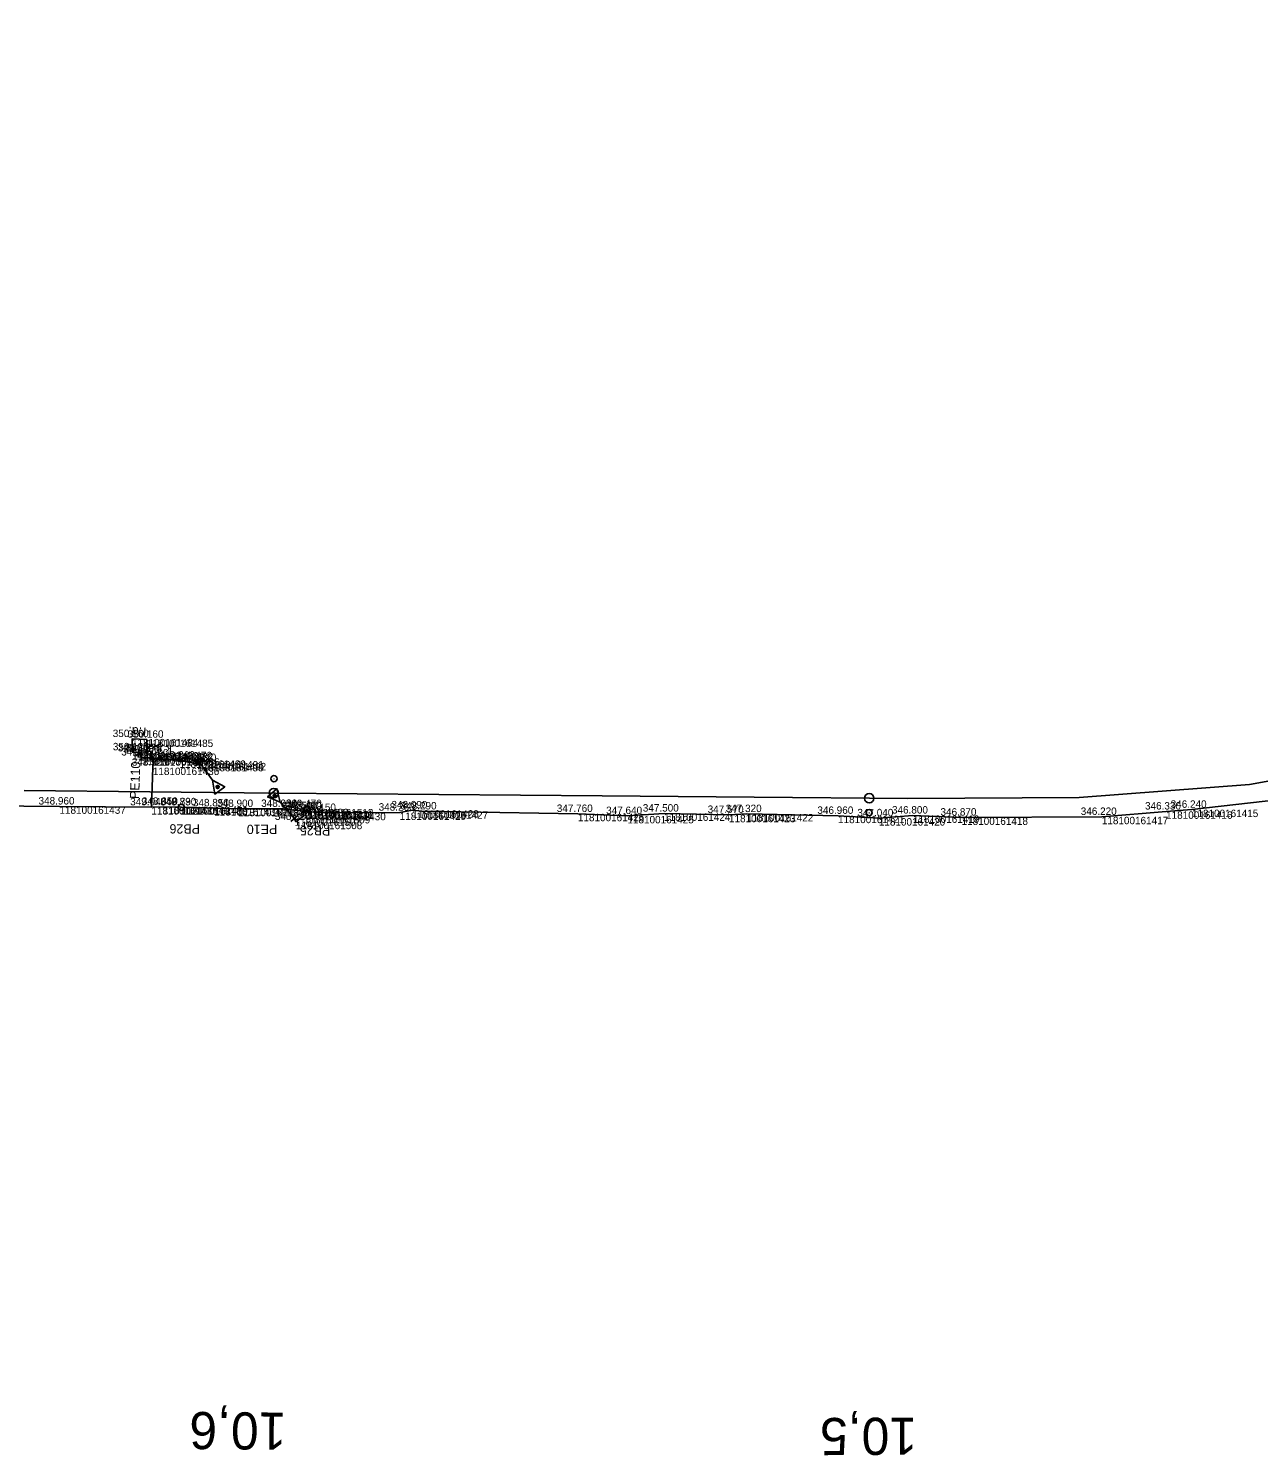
# Model space of a CAD drawing. Extents: x -732194 to -724760, y -944826 to -941477.
# Drawn here: x -727001.6 to -726803.1, y -942096.8 to -941866.5 of the extents above; entities that cross this region are included whole.
import ezdxf

# ---------------------------------------------------------------- set-up
doc = ezdxf.new("R2010")
doc.units = 0
for name, color, linetype in [('Vrstva 1', 7, 'Continuous'), ('Vrstva 25', 7, 'Continuous'), ('Vrstva 26', 7, 'Continuous'), ('Vrstva 28', 7, 'Continuous'), ('Vrstva 31', 7, 'Continuous'), ('Vrstva 35', 7, 'Continuous'), ('Vrstva 36', 7, 'Continuous'), ('Vrstva 4', 7, 'Continuous'), ('Vrstva 60', 7, 'Continuous'), ('Vrstva 61', 7, 'Continuous'), ('Vrstva 7', 7, 'Continuous')]:
    doc.layers.add(name, color=color, linetype=linetype)

msp = doc.modelspace()

# ---------------------------------------------------------------- linework, layer by layer
at = {"layer": 'Vrstva 1'}
msp.add_lwpolyline([(-726579.57, -941866.53), (-726589.02, -941872.75), (-726602.3, -941882.23), (-726613.83, -941891.22), (-726625.12, -941900.77), (-726638.15, -941911.63), (-726655.27, -941925.61), (-726667.22, -941934.63), (-726679.44, -941942.96), (-726693.78, -941951.66), (-726719.62, -941964.76), (-726748.05, -941975.61), (-726760.36, -941979.39), (-726775.65, -941983.31), (-726804.56, -941988.54), (-726832.05, -941990.67), (-726859.67, -941990.82), (-726884.47, -941990.59), (-726908.99, -941990.36), (-726961.75, -941989.93), (-727002.29, -941989.53)], dxfattribs=at)
at = {"layer": 'Vrstva 25'}
msp.add_lwpolyline([(-726981.83, -941983.22), (-726981.89, -941984.22), (-726983.89, -941984.1), (-726983.83, -941983.1), (-726981.83, -941983.22)], dxfattribs=at)
at = {"layer": 'Vrstva 26'}
for points in [[(-726983.77, -941983.51), (-726983.24, -941984.17), (-726981.43, -941984.32)], [(-726981.75, -941992.21), (-726981.52, -941985.82)], [(-726799.69, -941990.95), (-726813.85, -941992.61), (-726818.02, -941992.89), (-726828.39, -941993.76), (-726851.02, -941993.87), (-726858.86, -941993.54), (-726864.37, -941993.98), (-726870.95, -941993.59), (-726885.65, -941993.3), (-726888.55, -941993.44), (-726899.03, -941993.22), (-726904.94, -941993.62), (-726912.93, -941993.28), (-726938.13, -941992.88), (-726939.63, -941992.7), (-726941.68, -941993.07), (-726954.64, -941993.12), (-726956.62, -941992.91), (-726960.64, -941992.47), (-726967.75, -941992.48), (-726971.62, -941992.37), (-726976.88, -941992.2), (-726979.86, -941992.13), (-726981.75, -941992.21)]]:
    msp.add_lwpolyline(points, dxfattribs=at)
at = {"layer": 'Vrstva 28'}
for p, q in [((-726981.52, -941985.82), (-726981.43, -941984.32)), ((-726976.97, -941992.23), (-726976.87, -941992.23)), ((-726956.69, -941992.5), (-726956.59, -941992.5))]:
    msp.add_line(p, q, dxfattribs=at)
for points in [[(-726983.77, -941983.51), (-726983.24, -941984.17), (-726981.43, -941984.32)], [(-726981.43, -941984.32), (-726977.21, -941984.66), (-726974.34, -941985.23), (-726974.34, -941984.77), (-726973.95, -941985.06)], [(-726981.75, -941992.21), (-726981.52, -941985.82)], [(-726799.69, -941990.95), (-726813.85, -941992.61), (-726818.02, -941992.89), (-726828.39, -941993.76), (-726851.02, -941993.87), (-726858.86, -941993.54), (-726864.37, -941993.98), (-726870.95, -941993.59), (-726885.65, -941993.3), (-726888.55, -941993.44), (-726899.03, -941993.22), (-726904.94, -941993.62), (-726912.93, -941993.28), (-726938.13, -941992.88), (-726939.63, -941992.7), (-726941.68, -941993.07), (-726954.64, -941993.12), (-726956.62, -941992.91), (-726960.64, -941992.47), (-726967.75, -941992.48), (-726971.62, -941992.37), (-726976.88, -941992.2), (-726979.86, -941992.13), (-726981.75, -941992.21)], [(-726981.75, -941992.21), (-726996.59, -941992.08), (-727013.89, -941991.92), (-727018.46, -941992.07), (-727034.38, -941993.25), (-727040.22, -941993.1), (-727050.06, -941994.56), (-727054.5, -941995.33), (-727056.89, -941997.46), (-727059.11, -941996.17), (-727088.99, -942000.66), (-727092.7, -942002.01), (-727094.56, -942002.3)], [(-726976.88, -941992.2), (-726976.92, -941992.23)], [(-726958.65, -941994.02), (-726958.43, -941994.56), (-726957.15, -941993.63), (-726957.29, -941992.84)], [(-726956.67, -941992.79), (-726956.64, -941992.5)]]:
    msp.add_lwpolyline(points, dxfattribs=at)
for centre in [(-726976.92, -941992.23), (-726956.64, -941992.5)]:
    msp.add_circle(centre, 0.5, dxfattribs=at)
at = {"layer": 'Vrstva 31'}
for points in [[(-726799.69, -941990.95), (-726813.85, -941992.61), (-726818.02, -941992.89), (-726828.39, -941993.76), (-726851.02, -941993.87), (-726858.86, -941993.54), (-726864.37, -941993.98), (-726870.95, -941993.59), (-726885.65, -941993.3), (-726888.55, -941993.44), (-726899.03, -941993.22), (-726904.94, -941993.62), (-726912.93, -941993.28), (-726938.13, -941992.88), (-726939.63, -941992.7), (-726941.68, -941993.07), (-726954.64, -941993.12), (-726956.62, -941992.91), (-726960.64, -941992.47), (-726967.75, -941992.48), (-726971.62, -941992.37), (-726976.88, -941992.2), (-726979.86, -941992.13), (-726981.75, -941992.21)], [(-726981.75, -941992.21), (-726996.59, -941992.08), (-727013.89, -941991.92), (-727018.46, -941992.07), (-727034.38, -941993.25), (-727040.22, -941993.1), (-727050.06, -941994.56), (-727054.5, -941995.33), (-727056.89, -941997.46), (-727059.11, -941996.17), (-727088.99, -942000.66), (-727092.7, -942002.01), (-727094.56, -942002.3)]]:
    msp.add_lwpolyline(points, dxfattribs=at)
at = {"layer": 'Vrstva 35'}
for points in [[(-726981.75, -941992.21), (-726981.52, -941985.82)], [(-726956.62, -941992.91), (-726960.64, -941992.47), (-726967.75, -941992.48)]]:
    msp.add_lwpolyline(points, dxfattribs=at)
at = {"layer": 'Vrstva 36'}
msp.add_lwpolyline([(-726982.48, -941983.48), (-726984.84, -941983.33), (-726984.88, -941981.19), (-726982.49, -941981.3), (-726982.48, -941983.48)], dxfattribs=at)
at = {"layer": 'Vrstva 4'}
for p, q in [((-726973.32, -941984.6), (-726974.58, -941985.52)), ((-726971.03, -941988.71), (-726971.11, -941989.19)), ((-726961.89, -941990.65), (-726961.85, -941990.16)), ((-726959.24, -941994.53), (-726958.06, -941993.51))]:
    msp.add_line(p, q, dxfattribs=at)
for points in [[(-726973.95, -941985.06), (-726971.9, -941987.87), (-726969.92, -941988.9), (-726971.53, -941990.09), (-726971.9, -941987.87)], [(-726958.65, -941994.02), (-726960.95, -941991.41), (-726963.01, -941990.55), (-726961.51, -941989.23), (-726960.95, -941991.41)]]:
    msp.add_lwpolyline(points, dxfattribs=at)
for centre in [(-726971.07, -941988.95), (-726961.87, -941990.4)]:
    msp.add_circle(centre, 0.248, dxfattribs=at)
at = {"layer": 'Vrstva 60'}
for p, q in [((-726984.88, -941981.19), (-726984.88, -941981.19)), ((-726982.49, -941981.3), (-726982.49, -941981.3)), ((-726984.84, -941983.33), (-726984.84, -941983.33)), ((-726983.77, -941983.51), (-726983.77, -941983.51)), ((-726983.24, -941984.17), (-726983.24, -941984.17)), ((-726982.86, -941983.66), (-726982.86, -941983.66)), ((-726982.48, -941983.48), (-726982.48, -941983.48)), ((-726981.43, -941984.32), (-726981.43, -941984.32)), ((-726981.52, -941985.82), (-726981.52, -941985.82)), ((-726977.21, -941984.66), (-726977.21, -941984.66)), ((-726974.34, -941984.77), (-726974.34, -941984.77)), ((-726974.34, -941985.23), (-726974.34, -941985.23)), ((-726973.95, -941985.06), (-726973.95, -941985.06)), ((-726996.59, -941992.08), (-726996.59, -941992.08)), ((-726981.75, -941992.21), (-726981.75, -941992.21)), ((-726979.86, -941992.13), (-726979.86, -941992.13)), ((-726976.92, -941992.23), (-726976.92, -941992.23)), ((-726976.88, -941992.2), (-726976.88, -941992.2)), ((-726971.62, -941992.37), (-726971.62, -941992.37)), ((-726967.75, -941992.48), (-726967.75, -941992.48)), ((-726960.64, -941992.47), (-726960.64, -941992.47)), ((-726957.29, -941992.84), (-726957.29, -941992.84)), ((-726957.15, -941993.63), (-726957.15, -941993.63)), ((-726956.67, -941992.79), (-726956.67, -941992.79)), ((-726956.64, -941992.5), (-726956.64, -941992.5)), ((-726956.62, -941992.91), (-726956.62, -941992.91)), ((-726954.64, -941993.12), (-726954.64, -941993.12)), ((-726941.68, -941993.07), (-726941.68, -941993.07)), ((-726939.63, -941992.7), (-726939.63, -941992.7)), ((-726938.13, -941992.88), (-726938.13, -941992.88)), ((-726912.93, -941993.28), (-726912.93, -941993.28)), ((-726904.94, -941993.62), (-726904.94, -941993.62)), ((-726899.03, -941993.22), (-726899.03, -941993.22)), ((-726888.55, -941993.44), (-726888.55, -941993.44)), ((-726885.65, -941993.3), (-726885.65, -941993.3)), ((-726870.95, -941993.59), (-726870.95, -941993.59)), ((-726858.86, -941993.54), (-726858.86, -941993.54)), ((-726818.02, -941992.89), (-726818.02, -941992.89)), ((-726813.85, -941992.61), (-726813.85, -941992.61)), ((-726958.65, -941994.02), (-726958.65, -941994.02)), ((-726958.43, -941994.56), (-726958.43, -941994.56)), ((-726864.37, -941993.98), (-726864.37, -941993.98)), ((-726851.02, -941993.87), (-726851.02, -941993.87)), ((-726828.39, -941993.76), (-726828.39, -941993.76))]:
    msp.add_line(p, q, dxfattribs=at)
at = {"layer": 'Vrstva 7'}
for p, q in [((-726962.02, -941987.61), (-726961.92, -941987.61)), ((-726865.99, -941993.1), (-726865.89, -941993.11))]:
    msp.add_line(p, q, dxfattribs=at)
for centre, radius in [((-726961.97, -941987.61), 0.5), ((-726962, -941989.93), 0.75), ((-726865.92, -941990.76), 0.75), ((-726865.94, -941993.1), 0.5)]:
    msp.add_circle(centre, radius, dxfattribs=at)

# ---------------------------------------------------------------- texts
at = {"layer": 'Vrstva 25'}
msp.add_text('k.s.', height=1.5, rotation=176.3632, dxfattribs=at).set_placement((-726978.41, -941982.19))
at = {"layer": 'Vrstva 28'}
for s, rotation, p in [('PB26', 179.4375, (-726973.91, -941995)), ('PB25', 179.5341, (-726952.88, -941995.29))]:
    msp.add_text(s, height=1.5, rotation=rotation, dxfattribs=at).set_placement(p)
at = {"layer": 'Vrstva 36'}
for s, rotation, p in [('r.d.', 176.3632, (-726982.56, -941979.4)), ('PE110', 87.9386, (-726983.74, -941990.91)), ('PE10', 180.0806, (-726961.45, -941995.04))]:
    msp.add_text(s, height=1.5, rotation=rotation, dxfattribs=at).set_placement(p)
at = {"layer": 'Vrstva 60'}
for s, p in [('118100161484', (-726984.88, -941982.39)), ('118100161485', (-726982.49, -941982.5)), ('118100161483', (-726984.84, -941984.53)), ('118100161487', (-726983.77, -941984.71)), ('118100161488', (-726983.24, -941985.37)), ('118100161481', (-726982.86, -941984.86)), ('118100161482', (-726982.48, -941984.68)), ('118100161486', (-726981.43, -941985.52)), ('118100161436', (-726981.52, -941987.02)), ('118100161489', (-726977.21, -941985.86)), ('118100161491', (-726974.34, -941985.97)), ('118100161490', (-726974.34, -941986.43)), ('118100161492', (-726973.95, -941986.26)), ('118100161437', (-726996.59, -941993.28)), ('118100161435', (-726981.75, -941993.41)), ('118100161449', (-726979.86, -941993.33)), ('118100161480', (-726976.92, -941993.43)), ('118100161479', (-726976.88, -941993.4)), ('118100161434', (-726971.62, -941993.57)), ('118100161433', (-726967.75, -941993.68)), ('118100161432', (-726960.64, -941993.67)), ('118100161510', (-726957.29, -941994.04)), ('118100161509', (-726957.15, -941994.83)), ('118100161511', (-726956.67, -941993.99)), ('118100161512', (-726956.64, -941993.7)), ('118100161431', (-726956.62, -941994.11)), ('118100161430', (-726954.64, -941994.32)), ('118100161429', (-726941.68, -941994.27)), ('118100161428', (-726939.63, -941993.9)), ('118100161427', (-726938.13, -941994.08)), ('118100161426', (-726912.93, -941994.48)), ('118100161425', (-726904.94, -941994.82)), ('118100161424', (-726899.03, -941994.42)), ('118100161423', (-726888.55, -941994.64)), ('118100161422', (-726885.65, -941994.5)), ('118100161421', (-726870.95, -941994.79)), ('118100161419', (-726858.86, -941994.74)), ('118100161417', (-726828.39, -941994.96)), ('118100161416', (-726818.02, -941994.09)), ('118100161415', (-726813.85, -941993.81)), ('118100161507', (-726958.65, -941995.22)), ('118100161508', (-726958.43, -941995.76)), ('118100161420', (-726864.37, -941995.18)), ('118100161418', (-726851.02, -941995.07))]:
    msp.add_text(s, height=1.2, dxfattribs=at).set_placement(p)
at = {"layer": 'Vrstva 61'}
for s, p in [('350.160', (-726987.99, -941980.89)), ('350.160', (-726985.6, -941981)), ('350.120', (-726987.97, -941983.03)), ('349.350', (-726987.17, -941983.21)), ('350.080', (-726986.25, -941983.36)), ('350.370', (-726985.88, -941983.18)), ('349.260', (-726986.61, -941983.87)), ('348.920', (-726984.92, -941985.52)), ('349.290', (-726984.8, -941984.02)), ('349.360', (-726980.58, -941984.36)), ('349.470', (-726977.77, -941984.47)), ('349.320', (-726977.74, -941984.93)), ('350.120', (-726977.08, -941984.76)), ('348.960', (-726999.96, -941991.78)), ('349.040', (-726985.17, -941991.91)), ('348.850', (-726983.29, -941991.83)), ('348.830', (-726980.31, -941991.9)), ('349.790', (-726980.3, -941991.93)), ('348.850', (-726975.05, -941992.07)), ('348.900', (-726971.14, -941992.18)), ('348.930', (-726964.04, -941992.17)), ('348.500', (-726960.71, -941992.54)), ('348.490', (-726960.1, -941992.49)), ('349.470', (-726960.07, -941992.2)), ('348.990', (-726959.99, -941992.61)), ('348.090', (-726943.02, -941992.4)), ('348.290', (-726941.53, -941992.58)), ('346.330', (-726821.42, -941992.59)), ('346.240', (-726817.28, -941992.31)), ('349.540', (-726962.08, -941993.72)), ('348.620', (-726961.83, -941994.26)), ('348.440', (-726960.63, -941993.33)), ('349.150', (-726957.78, -941992.82)), ('348.260', (-726945.08, -941992.77)), ('347.760', (-726916.34, -941992.98)), ('347.640', (-726908.37, -941993.32)), ('347.500', (-726902.46, -941992.92)), ('347.570', (-726891.99, -941993.14)), ('347.320', (-726889.08, -941993)), ('346.960', (-726874.29, -941993.29)), ('347.040', (-726867.83, -941993.68)), ('346.800', (-726862.25, -941993.24)), ('346.870', (-726854.42, -941993.57)), ('346.220', (-726831.79, -941993.46))]:
    msp.add_text(s, height=1.2, dxfattribs=at).set_placement(p)
at = {"layer": 'Vrstva 7'}
for s, rotation, p in [('10,6', 179.5341, (-726959.96, -942089.94)), ('10,5', 180.3278, (-726858.24, -942090.72))]:
    msp.add_text(s, height=6, rotation=rotation, dxfattribs=at).set_placement(p)

doc.saveas('drawing.dxf')
